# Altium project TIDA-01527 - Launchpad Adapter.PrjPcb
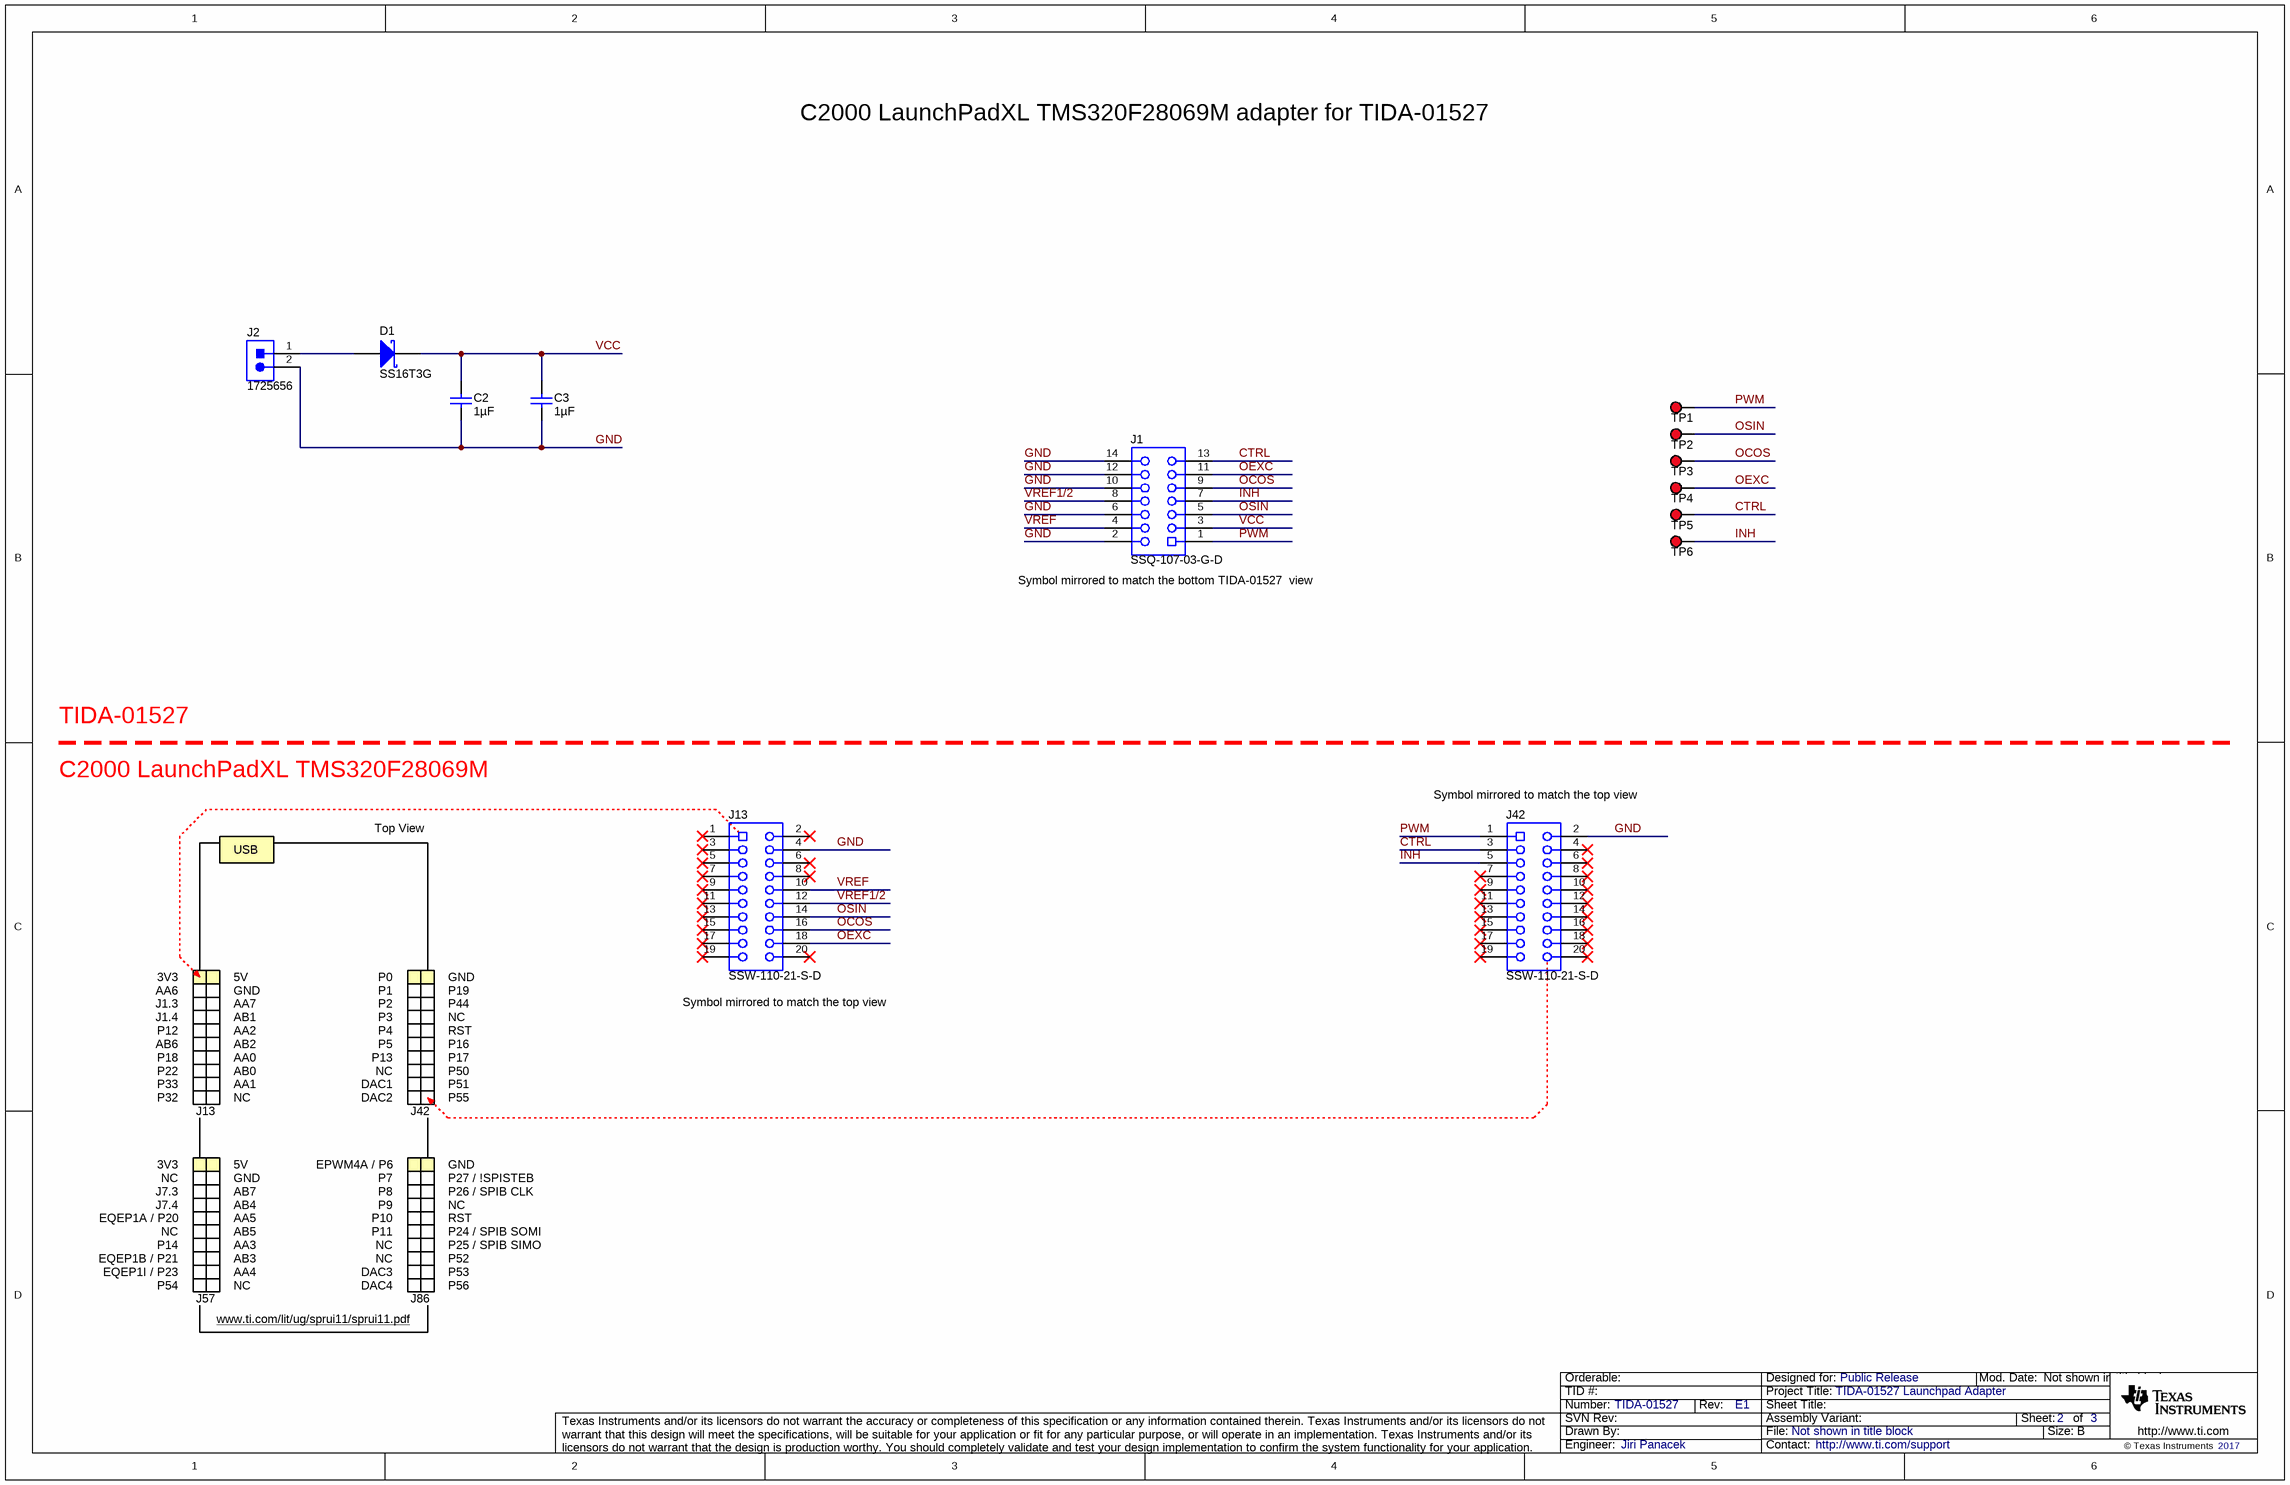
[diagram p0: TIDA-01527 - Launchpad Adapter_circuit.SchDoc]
CopyrightYear: 2017; PCB_Layout: Jiri Panacek; PCB_Rev: E1; PRJ_Customer: Public Release; PRJ_Engineer: Jiri Panacek; PRJ_Number: TIDA-01527; PRJ_Title: TIDA-01527 Launchpad Adapter; SCH_Rev: E1; TechSupport: http://www.ti.com/support
2 sheets, 20 parts. Net scope: global (net labels, ports and power ports of the same name join across sheets).
Board file: TIDA-01527 - Launchpad Adapter.PcbDoc
Sheets:
  TIDA-01527 - Launchpad Adapter_circuit.SchDoc
  TIDA-01527 - Launchpad Adapter_Hardware.SchDoc

## Sheet TIDA-01527 - Launchpad Adapter_circuit.SchDoc
size 431 x 279 mm; Date: Not shown in title block; ApprovedBy: Not shown in title block; CheckedBy: Not shown in title block; Author: Not shown in title block; CompanyName: Not shown in title block; Engineer: Not shown in title block; Organization: Not shown in title block; Address1: Not shown in title block; Address2: Not shown in title block; Address3: Not shown in title block; Address4: Not shown in title block; DocumentNumber: 1; Revision: Use project parameter SCH_Rev; SheetNumber: 2; SheetTotal: 3; PageSetup: Record=PageOptions¦CenterHorizontal=True¦CenterVertical=True¦PrintScale=1.00¦XCorrection=1.00¦YCorrection=1.00¦PrintKind=0¦BorderSize=5000000¦LeftOffset=0¦BottomOffset=0¦Orientation=2¦PaperLength=1000¦PaperWidth=1000¦Scale=100¦PaperSource=15¦PrintQuality=600¦MediaType=1¦DitherType=10¦PaperKind=Letter¦PrintScaleMode=1

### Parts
C2  ValueDisplayed: 1µF  [1206_180]  (hidden comment: GCM31CR72A105KA03)
C3  ValueDisplayed: 1µF  [1206_180]  (hidden comment: GCM31CR72A105KA03)
D1  SS16T3G  [SMA]
J1  SSQ-107-03-G-D  [SSQ-107-03-G-D]
J2  1725656  [CONN_1725656]
J13  SSW-110-21-S-D  [Samtec_SSW-110-x1-x-D]
J42  SSW-110-21-S-D  [Samtec_SSW-110-x1-x-D]
TP1  5005  [Keystone5005]  (value not drawn)
TP2  5005  [Keystone5005]  (value not drawn)
TP3  5005  [Keystone5005]  (value not drawn)
TP4  5005  [Keystone5005]  (value not drawn)
TP5  5005  [Keystone5005]  (value not drawn)
TP6  5005  [Keystone5005]  (value not drawn)

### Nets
CTRL: J1.13 J42.3 TP5.1
GND: C2.2 C3.2 J1.2 J1.6 J1.10 J1.12 J1.14 J2.2 J13.4 J42.2
INH: J1.7 J42.5 TP6.1
OCOS: J1.9 J13.16 TP3.1
OEXC: J1.11 J13.18 TP4.1
OSIN: J1.5 J13.14 TP2.1
PWM: J1.1 J42.1 TP1.1
VCC: C2.1 C3.1 D1.1(K) J1.3
VREF: J1.4 J13.10
VREF1/2: J1.8 J13.12
NetD1_2: D1.2(A) J2.1

Not connected (* = marked no-connect by the designer): J13 1* 2* 3* 5* 6* 7* 8* 9* 11* 13* 15* 17* 19* 20*; J42 4* 6* 7* 8* 9* 10* 11* 12* 13* 14* 15* 16* 17* 18* 19* 20*

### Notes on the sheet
- C2000 LaunchPadXL TMS320F28069M adapter for TIDA-01527
- (near J1) Symbol mirrored to match the bottom TIDA-01527  view
- TIDA-01527
- C2000 LaunchPadXL TMS320F28069M
- Top View
- (near J42) Symbol mirrored to match the top view
- USB
- 3V3
- 5V
- P0
- GND
- AA6
- J1.3
- J1.4
- P12
- AA7
- AB1
- AA2
- P1
- P2
- P3
- P4
- P19
- P44
- NC
- RST
- (near J13) Symbol mirrored to match the top view
- AB6
- P18
- P22
- P33
- P32
- J13
- AB2
- AA0
- AB0
- AA1
- P5
- P13
- DAC1
- DAC2
- J42
- P16
- P17
- P50
- P51
- P55
- EPWM4A / P6
- J7.3
- J7.4
- EQEP1A / P20
- P14
- AB7
- AB4
- AA5
- AB5
- AA3
- P7
- P8
- P9
- P10
- P11
- P27 / !SPISTEB
- P26 / SPIB CLK
- P24 / SPIB SOMI
- P25 / SPIB SIMO
- EQEP1B / P21
- EQEP1I / P23
- P54
- J57
- AB3
- AA4
- DAC3
- DAC4
- J86
- P52
- P53
- P56
- www.ti.com/lit/ug/sprui11/sprui11.pdf

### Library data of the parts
C2 C3 = GCM31CR72A105KA03: CAP, CERM, 1 µF, 100 V,+/- 10%, X7R, AEC-Q200 Grade 1, 1206; Manufacturer: MuRata; Polarized: N; CompType: Capacitor; Value: 1uF; U/M: EA; Cap_F: 0.000001; Tolerance_%: 10; VDC_V: 100; Value2: 100V; TaMin_C: -55; TaMax_C: 125; Cap_Case: 1206; AEC Category: Q200; AEC Qualified: Y; AEC Grade: 1; SizeArea_mm2: 5.12; SizeAreaWB_mm2: 10.92; SizeX_mm: 3.2; SizeY_mm: 1.6; SizeZ_mm: 1.8
D1 = SS16T3G: Diode, Schottky, 60 V, 1 A, SMA; Manufacturer: ON Semiconductor; U/M: EA; Vf_V: 0.72; Value: 60V; Value1: 1A; Value2: 0.72V; Io_A: 1; Vr_V: 60; TJmax_C: 125; RJC_CperW: 35; AEC Category: Q101
J1 = SSQ-107-03-G-D: Receptacle, 100mil, 7x2, Gold, TH; Manufacturer: Samtec; SymbolCreator: a0412235; CompType: Socket Strip
J2 = 1725656: Terminal Block, 100mil, 2x1, 6A, 63V, TH; Manufacturer: Phoenix Contact; SymbolCreator: a0412235; U/M: EA
J13 J42 = SSW-110-21-S-D: Receptacle, 2.54mm, 10x2, Gold, TH; Manufacturer: Samtec; SymbolCreator: a0412235; Pitch_mm: 2.54; Gender: Female; Row_Count: 2
TP1-TP6 = 5005: Test Point, Compact, Red, TH; Manufacturer: Keystone; CompType: Test Point Loop; ContactFinish: Silver; Green_Lifecycle: Active; Green_REACh: Passed

## Sheet TIDA-01527 - Launchpad Adapter_Hardware.SchDoc
size 431 x 279 mm; Date: Not shown in title block; ApprovedBy: Not shown in title block; CheckedBy: Not shown in title block; Author: Not shown in title block; CompanyName: Not shown in title block; Engineer: Not shown in title block; Organization: Not shown in title block; Address1: Not shown in title block; Address2: Not shown in title block; Address3: Not shown in title block; Address4: Not shown in title block; DocumentNumber: 1; Revision: Use project parameter SCH_Rev; SheetNumber: 3; SheetTotal: 3; PageSetup: Record=PageOptions¦CenterHorizontal=True¦CenterVertical=True¦PrintScale=1.00¦XCorrection=1.00¦YCorrection=1.00¦PrintKind=0¦BorderSize=5000000¦LeftOffset=0¦BottomOffset=0¦Orientation=2¦PaperLength=1000¦PaperWidth=1000¦Scale=100¦PaperSource=15¦PrintQuality=600¦MediaType=1¦DitherType=10¦PaperKind=Letter¦PrintScaleMode=1
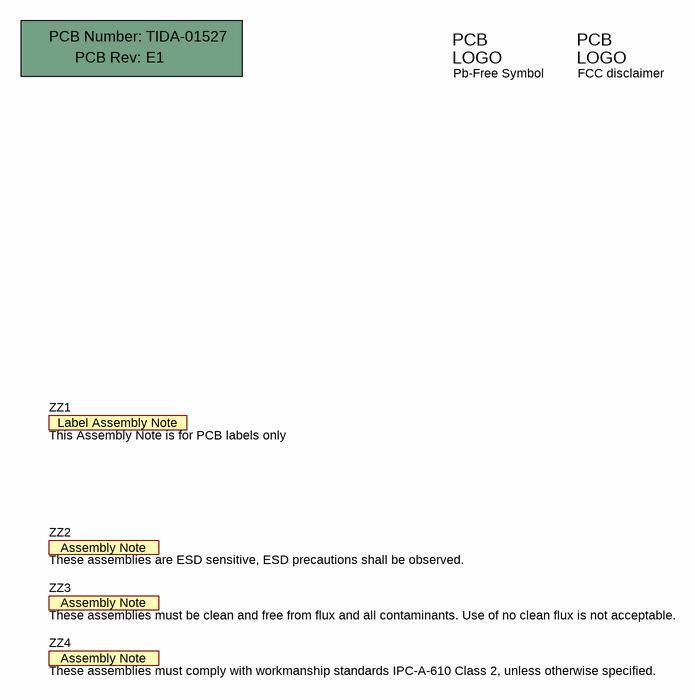
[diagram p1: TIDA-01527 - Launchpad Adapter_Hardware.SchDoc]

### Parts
!PCB  Printed Circuit Board  (value not drawn)  (mechanical)
Logo2  Pb-Free Symbol  [Pb-Free_Overlay_Small]  (no BOM)
Logo3  FCC disclaimer  [FCC_disclaimer]  (no BOM)
ZZ1  This Assembly Note is for PCB labels only  [AssemblyNoteLabel]  (no BOM)
ZZ2  These assemblies are ESD sensitive, ESD precautions shall be observed.  [AssemblyNote]  (no BOM)
ZZ3  These assemblies must be clean and free from flux and all contaminants. Use of no clean flux is not acceptable.  [AssemblyNote]  (no BOM)
ZZ4  These assemblies must comply with workmanship standards IPC-A-610 Class 2, unless otherwise specified.  [AssemblyNote]  (no BOM)

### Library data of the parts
!PCB = PCB: Manufacturer: Any; PartNumber: TIDA-01527; SymbolCreator: a0412235
Logo2 = Pb-Free: SymbolCreator: a0412235
Logo3 = FCC_disclaimer: SymbolCreator: codlsc
ZZ1 = AssemblyNoteLabel: SymbolCreator: a0412235
ZZ2-ZZ4 = AssemblyNote: SymbolCreator: codlsc

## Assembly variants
001: not fitted FID1 FID2 FID3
